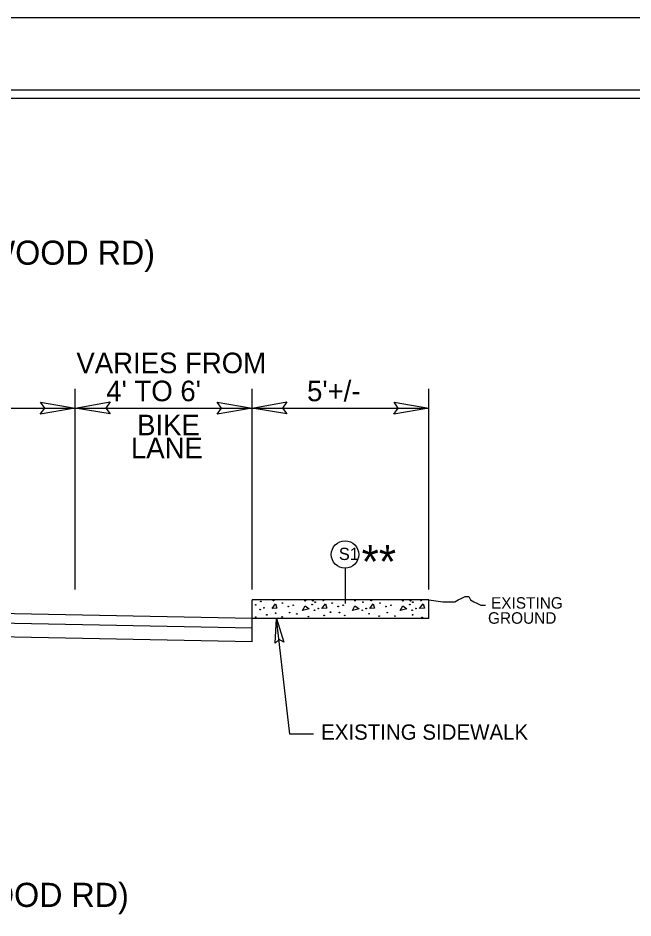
# Model space of a CAD drawing. Extents: x 1022283 to 1026986, y 174822 to 180471.
# Drawn here: x 1024154 to 1024632, y 179772 to 180471 of the extents above; entities that cross this region are included whole.
import ezdxf

# ---------------------------------------------------------------- set-up
doc = ezdxf.new("R2010")
doc.units = 0
for name, color, linetype in [('Default', 7, 'Continuous'), ('Prop Dimension', 7, 'Continuous'), ('Prop Terminator CELL', 7, 'Continuous'), ('Sheet Cutting Line CELL', 7, 'Continuous'), ('Sheet Plot Border Inside CELL', 7, 'Continuous'), ('Sheet Plot Border Outside CELL', 7, 'Continuous'), ('Sheet Typical CELL', 7, 'Continuous'), ('Typical Curb CELL', 7, 'Continuous'), ('Typical ID Circle CELL', 7, 'Continuous'), ('Typical Slope Point Local CELL', 7, 'Continuous'), ('Typical Text General CELL', 7, 'Continuous'), ('Typical Text ID Circle CELL', 7, 'Continuous')]:
    doc.layers.add(name, color=color, linetype=linetype)

# ---------------------------------------------------------------- blocks, each defined once
blk = doc.blocks.new('Terminator')
at = {"layer": 'Prop Terminator CELL'}
blk.add_lwpolyline([(-9, 1.55), (0, 0), (-9.05, -1.6), (-7.9, 0)], close=True, dxfattribs=at)

msp = doc.modelspace()

# ---------------------------------------------------------------- linework, layer by layer
at = {"layer": 'Default'}
for p, q in [((1024198.19, 180027.22), (1024198.19, 180183.23)), ((1024335.56, 180027.22), (1024335.56, 180183.23)), ((1024335.56, 180027.22), (1024335.56, 180183.23)), ((1024472.94, 180027.22), (1024472.94, 180183.23)), ((1024472.94, 180027.22), (1024472.94, 180183.23)), ((1024472.94, 180027.22), (1024472.94, 180183.23)), ((1023827.85, 180168.23), (1024335.56, 180168.23)), ((1023827.85, 180168.23), (1024335.56, 180168.23)), ((1024198.19, 180168.23), (1024335.56, 180168.23)), ((1024198.19, 180168.23), (1024335.56, 180168.23)), ((1024335.56, 180168.23), (1024472.94, 180168.23)), ((1024335.56, 180168.23), (1024472.94, 180168.23))]:
    msp.add_line(p, q, dxfattribs=at)
at = {"layer": 'Prop Dimension'}
for p, q in [((1024335.56, 180004.43), (1023827.85, 180014.58)), ((1024335.56, 180004.43), (1023827.85, 180014.58)), ((1024335.56, 179996.92), (1023827.85, 180007.08)), ((1024335.56, 179996.92), (1023827.85, 180007.08)), ((1024365.04, 179914.73), (1024354.68, 180004.43)), ((1024335.56, 179986.34), (1023827.85, 179996.5)), ((1024383.19, 179914.73), (1024365.04, 179914.73))]:
    msp.add_line(p, q, dxfattribs=at)
at = {"layer": 'Prop Terminator CELL'}
for points in [[(1024171.19, 180172.88), (1024198.19, 180168.23), (1024171.04, 180163.43), (1024174.49, 180168.23)], [(1024225.19, 180163.58), (1024198.19, 180168.23), (1024225.34, 180173.03), (1024221.89, 180168.23)], [(1024225.19, 180163.58), (1024198.19, 180168.23), (1024225.34, 180173.03), (1024221.89, 180168.23)], [(1024308.56, 180172.88), (1024335.56, 180168.23), (1024308.41, 180163.43), (1024311.86, 180168.23)], [(1024308.56, 180172.88), (1024335.56, 180168.23), (1024308.41, 180163.43), (1024311.86, 180168.23)], [(1024308.56, 180172.88), (1024335.56, 180168.23), (1024308.41, 180163.43), (1024311.86, 180168.23)], [(1024308.56, 180172.88), (1024335.56, 180168.23), (1024308.41, 180163.43), (1024311.86, 180168.23)], [(1024362.56, 180163.58), (1024335.56, 180168.23), (1024362.71, 180173.03), (1024359.26, 180168.23)], [(1024362.56, 180163.58), (1024335.56, 180168.23), (1024362.71, 180173.03), (1024359.26, 180168.23)], [(1024445.94, 180172.88), (1024472.94, 180168.23), (1024445.79, 180163.43), (1024449.24, 180168.23)], [(1024445.94, 180172.88), (1024472.94, 180168.23), (1024445.79, 180163.43), (1024449.24, 180168.23)]]:
    msp.add_lwpolyline(points, close=True, dxfattribs=at)
at = {"layer": 'Sheet Cutting Line CELL'}
msp.add_line((1026493.22, 180471.48), (1022283.22, 180471.48), dxfattribs=at)
at = {"layer": 'Sheet Plot Border Inside CELL'}
msp.add_lwpolyline([(1026481.97, 180415.35), (1022315.72, 180415.35), (1022315.72, 177777.6), (1026481.97, 177777.6)], close=True, dxfattribs=at)
at = {"layer": 'Sheet Plot Border Outside CELL'}
msp.add_lwpolyline([(1026493.22, 180471.48), (1022283.22, 180471.48), (1022283.22, 177721.48), (1026493.22, 177721.48)], close=True, dxfattribs=at)
at = {"layer": 'Sheet Typical CELL'}
msp.add_lwpolyline([(1026450.72, 180408.98), (1022700.72, 180408.98), (1022700.72, 177783.98), (1026450.72, 177783.98)], close=True, dxfattribs=at)
at = {"layer": 'Typical Curb CELL'}
for p, q in [((1024335.56, 179987.95), (1024335.56, 180018.95)), ((1024335.56, 180008.61), (1024335.56, 180018.95)), ((1024335.56, 180008.61), (1024335.56, 180018.95)), ((1024472.94, 180018.95), (1024335.56, 180018.95)), ((1024335.56, 179986.34), (1024335.56, 180018.95)), ((1024335.56, 179987.95), (1024335.56, 180018.95)), ((1024335.56, 180008.61), (1024335.56, 180018.95)), ((1024335.56, 180008.61), (1024335.56, 180018.95)), ((1024472.94, 180018.95), (1024335.56, 180018.95)), ((1024335.56, 179986.34), (1024335.56, 180018.95)), ((1024351.14, 180012.32), (1024353.82, 180016.04)), ((1024351.14, 180012.32), (1024353.82, 180016.04)), ((1024353.82, 180016.04), (1024354.88, 180012.52)), ((1024353.82, 180016.04), (1024354.88, 180012.52)), ((1024389.89, 180012.32), (1024392.54, 180016.04)), ((1024389.89, 180012.32), (1024392.54, 180016.04)), ((1024392.54, 180016.04), (1024393.61, 180012.52)), ((1024392.54, 180016.04), (1024393.61, 180012.52)), ((1024427.03, 180012.32), (1024429.71, 180016.04)), ((1024427.03, 180012.32), (1024429.71, 180016.04)), ((1024429.71, 180016.04), (1024430.77, 180012.52)), ((1024429.71, 180016.04), (1024430.77, 180012.52)), ((1024465.78, 180012.32), (1024468.43, 180016.04)), ((1024465.78, 180012.32), (1024468.43, 180016.04)), ((1024468.43, 180016.04), (1024469.5, 180012.52)), ((1024468.43, 180016.04), (1024469.5, 180012.52)), ((1024472.94, 180004.43), (1024472.94, 180018.95)), ((1024472.94, 180004.43), (1024472.94, 180018.95)), ((1024354.88, 180012.52), (1024351.14, 180012.32)), ((1024354.88, 180012.52), (1024351.14, 180012.32)), ((1024374.87, 180010.74), (1024376.81, 180014.29)), ((1024374.87, 180010.74), (1024376.81, 180014.29)), ((1024380.01, 180011.97), (1024374.87, 180010.74)), ((1024380.01, 180011.97), (1024374.87, 180010.74)), ((1024376.81, 180014.29), (1024380.01, 180011.97)), ((1024376.81, 180014.29), (1024380.01, 180011.97)), ((1024393.61, 180012.52), (1024389.89, 180012.32)), ((1024393.61, 180012.52), (1024389.89, 180012.32)), ((1024413.6, 180010.74), (1024415.54, 180014.29)), ((1024413.6, 180010.74), (1024415.54, 180014.29)), ((1024418.74, 180011.97), (1024413.6, 180010.74)), ((1024418.74, 180011.97), (1024413.6, 180010.74)), ((1024415.54, 180014.29), (1024418.74, 180011.97)), ((1024415.54, 180014.29), (1024418.74, 180011.97)), ((1024430.77, 180012.52), (1024427.03, 180012.32)), ((1024430.77, 180012.52), (1024427.03, 180012.32)), ((1024450.76, 180010.74), (1024452.7, 180014.29)), ((1024450.76, 180010.74), (1024452.7, 180014.29)), ((1024455.9, 180011.97), (1024450.76, 180010.74)), ((1024455.9, 180011.97), (1024450.76, 180010.74)), ((1024452.7, 180014.29), (1024455.9, 180011.97)), ((1024452.7, 180014.29), (1024455.9, 180011.97)), ((1024469.5, 180012.52), (1024465.78, 180012.32)), ((1024469.5, 180012.52), (1024465.78, 180012.32)), ((1024472.94, 180004.43), (1024335.56, 180004.43))]:
    msp.add_line(p, q, dxfattribs=at)
for centre in [(1024338.42, 180015.15), (1024338.42, 180015.15), (1024342.36, 180017.83), (1024342.36, 180017.83), (1024352.21, 180018.53), (1024352.21, 180018.53), (1024359.12, 180016.59), (1024359.12, 180016.59), (1024376.82, 180018.35), (1024376.82, 180018.35), (1024382.31, 180015.35), (1024382.31, 180015.35), (1024382.84, 180018.35), (1024382.84, 180018.35), (1024384.58, 180017.29), (1024384.58, 180017.29), (1024390.95, 180018.53), (1024390.95, 180018.53), (1024397.85, 180016.59), (1024397.85, 180016.59), (1024415.56, 180018.35), (1024415.56, 180018.35), (1024421.73, 180017.29), (1024421.73, 180017.29), (1024428.1, 180018.53), (1024428.1, 180018.53), (1024435.01, 180016.59), (1024435.01, 180016.59), (1024452.71, 180018.35), (1024452.71, 180018.35), (1024458.2, 180015.35), (1024458.2, 180015.35), (1024458.73, 180018.35), (1024458.73, 180018.35), (1024460.47, 180017.29), (1024460.47, 180017.29), (1024466.84, 180018.53), (1024466.84, 180018.53), (1024341.86, 180011.45), (1024341.86, 180011.45), (1024344.84, 180012.87), (1024344.84, 180012.87), (1024353.86, 180008.68), (1024353.86, 180008.68), (1024363.72, 180013.93), (1024363.72, 180013.93), (1024364.78, 180009.15), (1024364.78, 180009.15), (1024367.62, 180014.81), (1024367.62, 180014.81), (1024370.4, 180008.1), (1024370.4, 180008.1), (1024384.08, 180010.92), (1024384.08, 180010.92), (1024387.06, 180012.34), (1024387.06, 180012.34), (1024396.56, 180009.52), (1024396.56, 180009.52), (1024402.46, 180013.93), (1024402.46, 180013.93), (1024403.52, 180009.15), (1024403.52, 180009.15), (1024406.35, 180014.81), (1024406.35, 180014.81), (1024421.23, 180010.92), (1024421.23, 180010.92), (1024424.21, 180012.34), (1024424.21, 180012.34), (1024426.46, 180008.3), (1024426.46, 180008.3), (1024439.61, 180013.93), (1024439.61, 180013.93), (1024440.67, 180009.15), (1024440.67, 180009.15), (1024443.51, 180014.81), (1024443.51, 180014.81), (1024459.97, 180010.92), (1024459.97, 180010.92), (1024462.95, 180012.34), (1024462.95, 180012.34), (1024338.42, 180005.65), (1024338.42, 180005.65), (1024347.01, 180007.39), (1024347.01, 180007.39), (1024358.96, 180005.78), (1024358.96, 180005.78), (1024379.37, 180006.03), (1024379.37, 180006.03), (1024391.58, 180007), (1024391.58, 180007), (1024407.54, 180007), (1024407.54, 180007), (1024434.34, 180006.42), (1024434.34, 180006.42), (1024446.62, 180006.42), (1024446.62, 180006.42), (1024460.31, 180007.39), (1024460.31, 180007.39), (1024467.74, 180005.45), (1024467.74, 180005.45)]:
    msp.add_circle(centre, 0.249, dxfattribs=at)
at = {"layer": 'Typical ID Circle CELL'}
msp.add_line((1024407.81, 180043.68), (1024407.81, 180016.15), dxfattribs=at)
msp.add_circle((1024407.81, 180054.33), 10.65, dxfattribs=at)
at = {"layer": 'Typical Slope Point Local CELL'}
msp.add_lwpolyline([(1024472.94, 180018.95), (1024483.71, 180017.61), (1024486.4, 180017.61), (1024490.45, 180017.61), (1024493.14, 180017.61), (1024495.83, 180018.95), (1024498.52, 180020.3), (1024501.22, 180021.66), (1024503.91, 180021.66), (1024505.26, 180018.95), (1024507.95, 180017.61), (1024510.65, 180016.26), (1024513.34, 180014.92), (1024516.03, 180014.92), (1024517.09, 180014.92)], dxfattribs=at)
msp.add_lwpolyline([(1024472.94, 180018.95), (1024483.71, 180017.61), (1024486.4, 180017.61), (1024490.45, 180017.61), (1024493.14, 180017.61), (1024495.83, 180018.95), (1024498.52, 180020.3), (1024501.22, 180021.66), (1024503.91, 180021.66), (1024505.26, 180018.95), (1024507.95, 180017.61), (1024510.65, 180016.26), (1024513.34, 180014.92), (1024516.03, 180014.92), (1024517.09, 180014.92)], dxfattribs=at)

# ---------------------------------------------------------------- block references
at = {"layer": 'Prop Dimension', "xscale": 2.0767499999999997, "yscale": 2.076749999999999, "rotation": 96.5883266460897}
msp.add_blockref('Terminator', (1024354.68, 180004.43), dxfattribs=at)

# ---------------------------------------------------------------- texts
at = {"layer": 'Prop Dimension'}
for s, height, p in [('-EL- US 19/23 BUS (HAYWOOD RD) ', 18.75, (1023843.57, 180279.64)), ('VARIES FROM ', 16, (1024199.07, 180195.28)), ("5'+/-", 16, (1024378.32, 180173.5)), ("4' TO 6'", 16, (1024222.28, 180173.5)), ('BIKE', 16, (1024246.24, 180147.03)), ('LANE', 16, (1024241.48, 180129.19)), ('-EL- US 19/23 BUS (HAYWOOD RD) ', 18.75, (1023823.22, 179780.3))]:
    msp.add_text(s, height=height, dxfattribs=at).set_placement(p)
at = {"layer": 'Typical Slope Point Local CELL'}
for s, height, p in [('**', 25.771, (1024420.68, 180035.94)), ('EXISTING ', 8.938, (1024521.26, 180012.2)), ('EXISTING ', 8.938, (1024521.26, 180012.2)), ('GROUND', 8.938, (1024518.93, 180000.48)), ('GROUND', 8.938, (1024518.93, 180000.48))]:
    msp.add_text(s, height=height, dxfattribs=at).set_placement(p)
at = {"layer": 'Typical Text General CELL'}
msp.add_text('EXISTING SIDEWALK', height=11.8979, dxfattribs=at).set_placement((1024389.23, 179910.3))
at = {"layer": 'Typical Text ID Circle CELL'}
msp.add_text('S1', height=9.534, dxfattribs=at).set_placement((1024403.01, 180050.03))

doc.saveas('drawing.dxf')
